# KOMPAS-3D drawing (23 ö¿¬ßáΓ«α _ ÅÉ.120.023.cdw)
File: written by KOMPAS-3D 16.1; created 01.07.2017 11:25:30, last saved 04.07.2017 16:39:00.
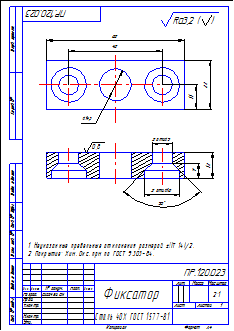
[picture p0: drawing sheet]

Sheet 1: A4, portrait

Title block, sheet 1: name: Фиксатор; designation: ПР.120.023; material: Сталь 40Х ГОСТ 1577-81; scale: 2:1; sheets: 1; sheet format: A4; stored path: D:\VSE\Эрга\Оснастка\Гибка лепестков\Прохвост\Скоба _ К17.479.019.cdw; drawn by: Сигачев СИ

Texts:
  Sergey
  Неуказанные предельные отклонения размеров  (IT 14)/2.
  Покрытие: Хим. Окс. прм по ГОСТ 9.303-84.
  Ra3,2
  Ra3,2 ( )
Dimensions and other numbers on the sheet: 42; 62; 11; 22; 14,5; 2 отв.; 9; 0,8; 7; 12; 16; 2:1; 1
